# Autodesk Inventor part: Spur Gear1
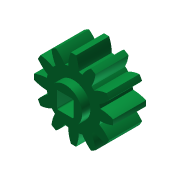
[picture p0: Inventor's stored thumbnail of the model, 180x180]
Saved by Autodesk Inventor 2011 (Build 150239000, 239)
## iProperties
Created: 2010-04
Part Number: Spur Gear1
Material: ABS Plastic
Document SubType Name: Modeling
Designer: Phil
Categories: <?xml version="1.0" encoding="UTF-16"?> <MemberInstance><Categories><FamilyTemplate><FamilyTemplateParameter ValueType="xs:double" Id="1" ObjectReferenceKey="da
Mass: 0.913644 g
Surface Area: 9.47061 cm^2
Volume: 0.861929 cm^3
Density: 1.06 g/cm^3
CustomPartVersion: 1
Author: Phil
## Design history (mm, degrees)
sketch "Sketch1"
  geometry: C1 r 7.62 at (0, 0)
  constraints: 1 centre point
  dimensions: "d0" = 15.24 diameter of C1 (= da_da)
extrude "Extrusion1" new body sketch "Sketch1" distance "d1" = 6.35 (= da_b); taper "d2" = 0 deg
sketch "Sketch2"
  geometry: C1 r 7.62 at (0, 0) reference; C2 r 6.35 at (0, 0)
  constraints: 1 centre point, 1 coincident
  dimensions: "d3" = 12.7 diameter of C2 (= da_dw)
feature "Pitch Diameter" sketch "Sketch2" dims "d4" = 76.2, "d5" = 0
workplane "Work Plane1"
workplane "Work Plane2"
workplane "Work Plane3"
feature "Spur Gear" dims "da_b" = 6.35, "da_d" = 12.7, "da_aw" = 50.8, "da_da" = 15.24, "da_df" = 10.4775, "da_dw" = 12.7, angle "da_beta" = 0 deg, "da_lefttooth" = 0, "da_righttooth" = 0
workplane "Work Plane4"
sketch "Sketch3"
  geometry: C1 r 3.251 at (0.498, -7.604); A1 r 7.62 centre (0.498, -7.604) between (-2.872, -0.77) and (-3.735, -1.268) reference; A2 r 7.62 centre (0.498, -7.604) between (-2.872, -0.77) and (-3.735, -1.268) reference; 1 further point
  constraints: 1 centre point, 1 coincident
  dimensions: "d20" = 6.5024 diameter of C1
extrude "Extrusion2" join sketch "Sketch3" stored distance "d21" = 9.525; taper "d22" = 0 deg
sketch "Sketch4"
  geometry: L1 (-1.359, -1.613)-(1.359, -1.613); L2 (1.613, -1.359)-(1.613, 1.359); L3 (1.359, 1.613)-(-1.359, 1.613); L4 (-1.613, 1.359)-(-1.613, -1.359); C1 r 3.251 at (0, 0) reference; A1 r 0.254 centre (-1.359, 1.359) between (-1.359, 1.613) and (-1.613, 1.359); A2 r 0.254 centre (1.359, 1.359) between (1.613, 1.359) and (1.359, 1.613); A3 r 0.254 centre (1.359, -1.359) between (1.359, -1.613) and (1.613, -1.359); A4 r 0.254 centre (-1.359, -1.359) between (-1.613, -1.359) and (-1.359, -1.613); 4 further points
  constraints: 8 end point, 8 point on circle, 8 tangent, 4 centre point, 4 point on line, 3 equal radius, 2 midpoint, 2 parallel, 2 perpendicular, 1 horizontal, 1 horizontal alignment, 1 vertical alignment
  dimensions: "d23" = 3.2258 distance of point (1.613, 1.613) point (-1.613, 1.613); "d24" = 0.254 radius of A1
extrude "Extrusion3" cut sketch "Sketch4" stored distance "d25" = 9.525; taper "d26" = 0 deg
body "Solid1"
body "Srf1"
node "Projected Loop1"
other parameters: "d6" = 0, "d7" = 15 deg (computed from da_z), "d9" = 0, "d14" = 0, "d15" = 50.8 (= da_aw), "d16" = 0, "d17" = 0, "d18" = 0, "d19" = 50.8 (= da_aw)
